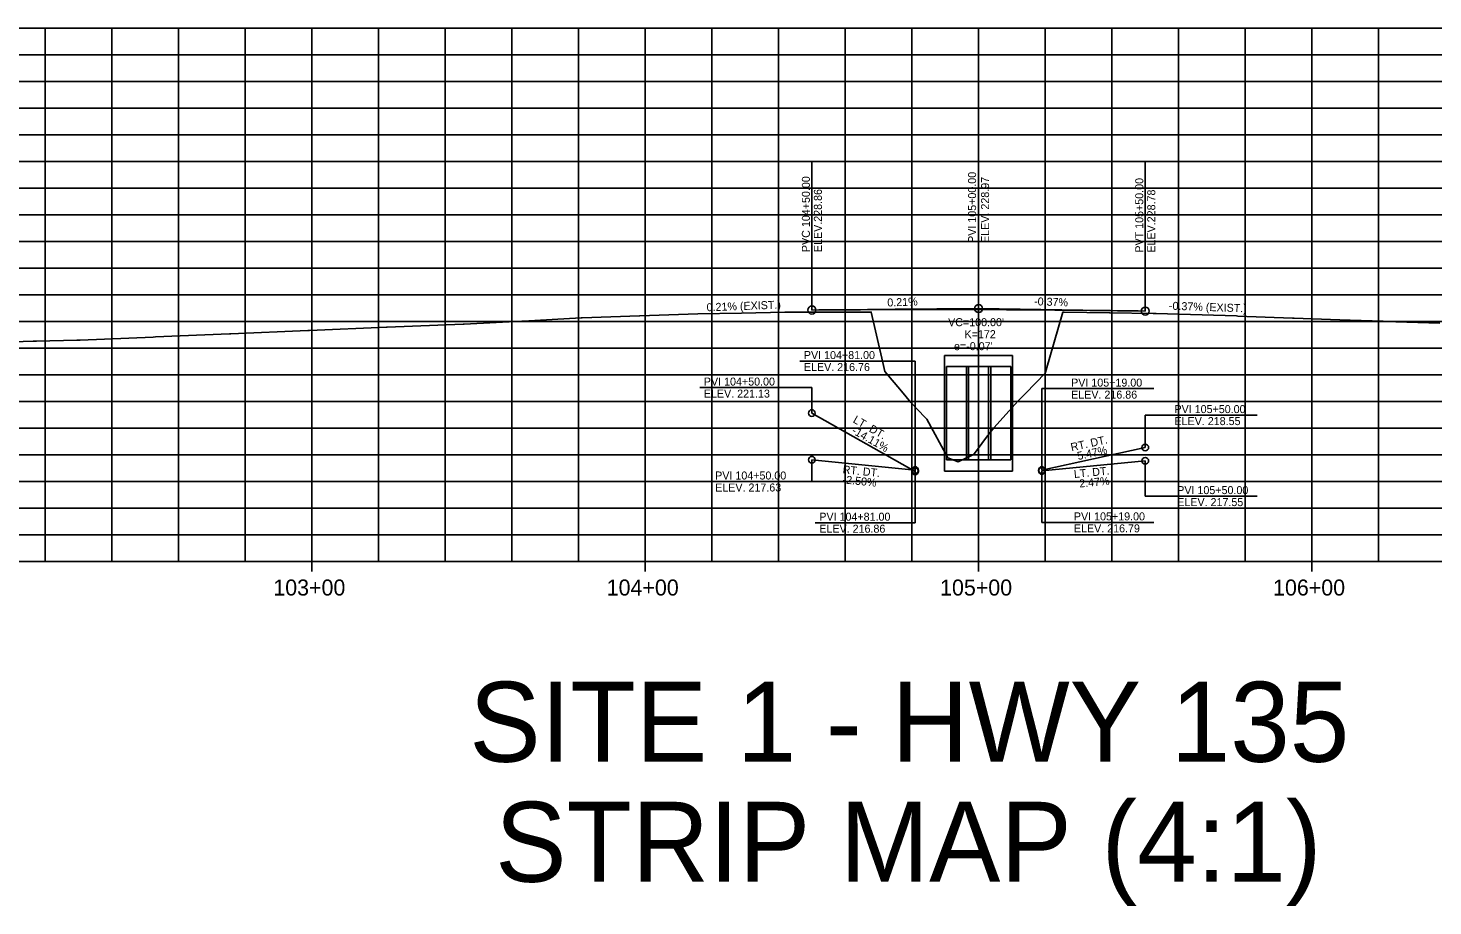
# Model space of a CAD drawing. Extents: x 1805251 to 1808760, y 516965 to 518393.
# Drawn here: x 1805687.1 to 1806108.5, y 518127.1 to 518390.4 of the extents above; entities that cross this region are included whole.
import ezdxf

# ---------------------------------------------------------------- set-up
doc = ezdxf.new("R2010")
doc.units = 0
for name, color, linetype in [('Default', 7, 'Continuous'), ('R_Axis', 7, 'Continuous'), ('R_Axis Annot', 7, 'Continuous'), ('R_Concrete', 7, 'Continuous'), ('R_Exist Surface', 7, 'Continuous'), ('R_Grid', 7, 'Continuous'), ('R_Vert Alg', 7, 'Continuous'), ('R_Vert Alg Annot', 7, 'Continuous')]:
    doc.layers.add(name, color=color, linetype=linetype)

msp = doc.modelspace()

# ---------------------------------------------------------------- linework, layer by layer
at = {"layer": 'R_Axis'}
msp.add_line((1805472.2, 518230.42), (1806472.2, 518230.42), dxfattribs=at)
at = {"layer": 'R_Concrete'}
for p, q in [((1805961.99, 518292.23), (1805982.41, 518292.23)), ((1805961.99, 518257.56), (1805961.99, 518292.23)), ((1805982.41, 518292.23), (1805982.41, 518257.56)), ((1805962.53, 518288.9), (1805981.87, 518288.9)), ((1805962.53, 518288.9), (1805962.53, 518260.9)), ((1805968.53, 518288.9), (1805968.53, 518260.9)), ((1805969.2, 518288.9), (1805969.2, 518260.9)), ((1805975.2, 518288.9), (1805975.2, 518260.9)), ((1805975.87, 518288.9), (1805975.87, 518260.9)), ((1805981.87, 518288.9), (1805981.87, 518260.9)), ((1805981.87, 518260.9), (1805962.53, 518260.9)), ((1805982.41, 518257.56), (1805961.99, 518257.56))]:
    msp.add_line(p, q, dxfattribs=at)
at = {"layer": 'R_Exist Surface'}
msp.add_lwpolyline([(1805676.49, 518296.16), (1805688.59, 518296.47), (1805689.59, 518296.49), (1805701.69, 518296.81), (1805702.68, 518296.84), (1805724.58, 518297.76), (1805725.32, 518297.79), (1805747.47, 518298.72), (1805747.96, 518298.75), (1805771.03, 518299.74), (1805771.46, 518299.76), (1805794.6, 518300.75), (1805794.8, 518300.76), (1805817.57, 518301.58), (1805817.91, 518301.59), (1805835.21, 518302.53), (1805835.6, 518302.55), (1805852.98, 518303.5), (1805853.3, 518303.51), (1805870.48, 518304.09), (1805870.64, 518304.1), (1805887.98, 518304.68), (1805888, 518304.68), (1805901.06, 518304.94), (1805901.08, 518304.94), (1805914.13, 518305.19), (1805914.17, 518305.19), (1805926.83, 518305.2), (1805927.09, 518305.21), (1805939.54, 518305.22), (1805940.02, 518305.23), (1805943.44, 518290.16), (1805944.09, 518287.4), (1805949.05, 518281.56), (1805951.9, 518278.14), (1805956.15, 518273.65), (1805956.64, 518273.14), (1805962.96, 518261.56), (1805962.97, 518261.53), (1805962.99, 518261.53), (1805966.1, 518260.34), (1805970.5, 518262.43), (1805970.66, 518262.45), (1805974.59, 518267.68), (1805976.76, 518270.55), (1805984.06, 518278.64), (1805984.14, 518278.72), (1805984.27, 518278.84), (1805986.23, 518280.85), (1805992.23, 518286.98), (1805992.46, 518287.88), (1805997.49, 518305.26), (1805997.91, 518305.25), (1806011.45, 518305.04), (1806011.66, 518305.04), (1806024.53, 518304.84), (1806025.42, 518304.83), (1806025.44, 518304.83), (1806049.53, 518304.07), (1806050, 518304.05), (1806066.4, 518303.44), (1806066.89, 518303.42), (1806083.26, 518302.81), (1806083.69, 518302.79), (1806096.89, 518302.38), (1806097.39, 518302.36), (1806110.51, 518301.95)], dxfattribs=at)
at = {"layer": 'R_Grid'}
for p, q in [((1805472.2, 518390.42), (1806472.2, 518390.42)), ((1805472.2, 518390.42), (1806472.2, 518390.42)), ((1805692.2, 518230.42), (1805692.2, 518390.42)), ((1805712.2, 518230.42), (1805712.2, 518390.42)), ((1805732.2, 518230.42), (1805732.2, 518390.42)), ((1805752.2, 518230.42), (1805752.2, 518390.42)), ((1805772.2, 518230.42), (1805772.2, 518390.42)), ((1805792.2, 518230.42), (1805792.2, 518390.42)), ((1805812.2, 518230.42), (1805812.2, 518390.42)), ((1805832.2, 518230.42), (1805832.2, 518390.42)), ((1805852.2, 518230.42), (1805852.2, 518390.42)), ((1805872.2, 518230.42), (1805872.2, 518390.42)), ((1805892.2, 518230.42), (1805892.2, 518390.42)), ((1805912.2, 518230.42), (1805912.2, 518390.42)), ((1805932.2, 518230.42), (1805932.2, 518390.42)), ((1805952.2, 518230.42), (1805952.2, 518390.42)), ((1805972.2, 518230.42), (1805972.2, 518390.42)), ((1805992.2, 518230.42), (1805992.2, 518390.42)), ((1806012.2, 518230.42), (1806012.2, 518390.42)), ((1806032.2, 518230.42), (1806032.2, 518390.42)), ((1806052.2, 518230.42), (1806052.2, 518390.42)), ((1806072.2, 518230.42), (1806072.2, 518390.42)), ((1806092.2, 518230.42), (1806092.2, 518390.42)), ((1805472.2, 518382.42), (1806472.2, 518382.42)), ((1805472.2, 518374.42), (1806472.2, 518374.42)), ((1805472.2, 518366.42), (1806472.2, 518366.42)), ((1805472.2, 518358.42), (1806472.2, 518358.42)), ((1805472.2, 518350.42), (1806472.2, 518350.42)), ((1805472.2, 518342.42), (1806472.2, 518342.42)), ((1805472.2, 518334.42), (1806472.2, 518334.42)), ((1805472.2, 518326.42), (1806472.2, 518326.42)), ((1805472.2, 518318.42), (1806472.2, 518318.42)), ((1805472.2, 518310.42), (1806472.2, 518310.42)), ((1805472.2, 518302.42), (1806472.2, 518302.42)), ((1805472.2, 518294.42), (1806472.2, 518294.42)), ((1805472.2, 518286.42), (1806472.2, 518286.42)), ((1805472.2, 518278.42), (1806472.2, 518278.42)), ((1805472.2, 518270.42), (1806472.2, 518270.42)), ((1805472.2, 518262.42), (1806472.2, 518262.42)), ((1805472.2, 518254.42), (1806472.2, 518254.42)), ((1805472.2, 518246.42), (1806472.2, 518246.42)), ((1805472.2, 518238.42), (1806472.2, 518238.42)), ((1805772.2, 518227.42), (1805772.2, 518230.42)), ((1805872.2, 518227.42), (1805872.2, 518230.42)), ((1805972.2, 518227.42), (1805972.2, 518230.42)), ((1806072.2, 518227.42), (1806072.2, 518230.42))]:
    msp.add_line(p, q, dxfattribs=at)
at = {"layer": 'R_Vert Alg'}
for p, q in [((1805947.2, 518306.07), (1805972.2, 518306.29)), ((1805972.2, 518306.29), (1805997.2, 518305.91)), ((1805922.2, 518274.95), (1805953.2, 518257.46)), ((1805991.2, 518257.86), (1806022.2, 518264.63)), ((1805922.2, 518260.95), (1805953.2, 518257.86)), ((1805991.2, 518257.58), (1806022.2, 518260.63))]:
    msp.add_line(p, q, dxfattribs=at)
msp.add_lwpolyline([(1805922.2, 518305.86), (1805924.28, 518305.88), (1805926.37, 518305.9), (1805928.45, 518305.91), (1805930.53, 518305.93), (1805932.62, 518305.94), (1805934.7, 518305.95), (1805936.78, 518305.96), (1805938.87, 518305.97), (1805940.95, 518305.98), (1805943.03, 518305.99), (1805945.12, 518306), (1805947.2, 518306), (1805949.28, 518306.01), (1805951.37, 518306.01), (1805953.45, 518306.01), (1805955.53, 518306.02), (1805957.62, 518306.02), (1805959.7, 518306.02), (1805961.78, 518306.02), (1805963.87, 518306.01), (1805965.95, 518306.01), (1805968.03, 518306.01), (1805970.12, 518306), (1805974.28, 518305.99), (1805976.37, 518305.98), (1805978.45, 518305.97), (1805980.53, 518305.96), (1805982.62, 518305.95), (1805984.7, 518305.94), (1805986.78, 518305.92), (1805988.87, 518305.91), (1805990.95, 518305.89), (1805993.03, 518305.88), (1805995.12, 518305.86), (1805997.2, 518305.84), (1805999.28, 518305.82), (1806001.37, 518305.8), (1806003.45, 518305.78), (1806005.53, 518305.76), (1806007.62, 518305.74), (1806009.7, 518305.71), (1806011.78, 518305.69), (1806013.87, 518305.66), (1806015.95, 518305.63), (1806018.03, 518305.6), (1806020.12, 518305.57), (1806022.2, 518305.54)], dxfattribs=at)
at = {"layer": 'R_Vert Alg Annot'}
for p, q in [((1805922.2, 518350.42), (1805922.2, 518305.86)), ((1805972.2, 518306.29), (1805972.2, 518350.42)), ((1806022.2, 518350.42), (1806022.2, 518305.54)), ((1805918.6, 518290.55), (1805953.2, 518290.55)), ((1805953.2, 518257.46), (1805953.2, 518290.55)), ((1805888.6, 518282.59), (1805922.2, 518282.59)), ((1805922.2, 518274.95), (1805922.2, 518282.59)), ((1805991.2, 518257.86), (1805991.2, 518282.28)), ((1805991.2, 518282.28), (1806024.8, 518282.28)), ((1806022.2, 518264.63), (1806022.2, 518274.34)), ((1806022.2, 518274.34), (1806055.8, 518274.34)), ((1805922.2, 518260.95), (1805922.2, 518254.42)), ((1806022.2, 518260.63), (1806022.2, 518250.04)), ((1805953.2, 518257.86), (1805953.2, 518242.06)), ((1805991.2, 518257.58), (1805991.2, 518242.16)), ((1805891.99, 518254.42), (1805922.2, 518254.42)), ((1806022.2, 518250.04), (1806055.8, 518250.04)), ((1805923.23, 518242.06), (1805953.2, 518242.06)), ((1805991.2, 518242.16), (1806024.8, 518242.16))]:
    msp.add_line(p, q, dxfattribs=at)
for centre, radius in [((1805922.2, 518305.86), 1.2), ((1805972.2, 518306.29), 1.2), ((1806022.2, 518305.54), 1.2), ((1805922.2, 518274.95), 1), ((1806022.2, 518264.63), 1), ((1805922.2, 518260.95), 1), ((1806022.2, 518260.63), 1), ((1805953.2, 518257.86), 1), ((1805953.2, 518257.46), 1), ((1805991.2, 518257.86), 1), ((1805991.2, 518257.58), 1)]:
    msp.add_circle(centre, radius, dxfattribs=at)

# ---------------------------------------------------------------- texts
at = {"layer": 'Default'}
for s, p in [('SITE 1 - HWY 135', (1805819.44, 518170.35)), ('STRIP MAP (4:1)', (1805827.19, 518134.35))]:
    msp.add_text(s, height=24, dxfattribs=at).set_placement(p)
at = {"layer": 'R_Axis Annot'}
for s, p in [('103+00', (1805760.66, 518220.22)), ('104+00', (1805860.66, 518220.22)), ('105+00', (1805960.66, 518220.22)), ('106+00', (1806060.54, 518220.22))]:
    msp.add_text(s, height=4.8, dxfattribs=at).set_placement(p)
at = {"layer": 'R_Vert Alg Annot'}
for s, rotation, p in [('PVC 104+50.00', 90, (1805921.6, 518323.23)), ('PVI 105+00.00', 90, (1805971.45, 518325.98)), ('ELEV. 228.97', 90, (1805975.35, 518325.98)), ('PVT 105+50.00', 90, (1806021.6, 518323.07)), ('ELEV.228.86', 90, (1805925.2, 518323.23)), ('ELEV.228.78', 90, (1806025.2, 518323.07)), ('0.21% (EXIST.)', 2.1461, (1805890.67, 518305.46)), ('0.21%', 2.1461, (1805944.87, 518306.9)), ('-0.37%', 358.0375, (1805988.82, 518307.29)), ('-0.37% (EXIST.)', 358.0375, (1806029.27, 518305.96)), ('LT. DT.', 330.557, (1805934.32, 518272.25)), ('-14.11%', 330.557, (1805933.97, 518269)), ('RT. DT.', 12.3349, (1806000.1, 518263.49)), ('5.47%', 12.3349, (1806002.08, 518260.85)), ('-2.50%', 354.2926, (1805931.34, 518253.87)), ('RT. DT.', 354.2926, (1805931.35, 518256.88)), ('LT. DT.', 5.6353, (1806000.91, 518255.46)), ('2.47%', 5.6353, (1806002.52, 518252.6))]:
    msp.add_text(s, height=2.4, rotation=rotation, dxfattribs=at).set_placement(p)
for s, p in [("VC=100.00'", (1805963.06, 518301.01)), ('K=172', (1805967.99, 518297.41)), ('PVI 104+81.00', (1805919.8, 518291.15)), ("e=-0.07'", (1805964.83, 518293.81)), ('ELEV. 216.76', (1805919.8, 518287.55)), ('PVI 104+50.00', (1805889.8, 518283.19)), ('PVI 105+19.00', (1805999.96, 518282.88)), ('ELEV. 221.13', (1805889.8, 518279.59)), ('ELEV. 216.86', (1805999.96, 518279.28)), ('PVI 105+50.00', (1806030.96, 518274.94)), ('ELEV. 218.55', (1806030.96, 518271.34)), ('PVI 104+50.00', (1805893.19, 518255.02)), ('ELEV. 217.63', (1805893.19, 518251.42)), ('PVI 105+50.00', (1806031.79, 518250.64)), ('ELEV. 217.55', (1806031.79, 518247.04)), ('PVI 104+81.00', (1805924.43, 518242.66)), ('PVI 105+19.00', (1806000.79, 518242.76)), ('ELEV. 216.86', (1805924.43, 518239.06)), ('ELEV. 216.79', (1806000.79, 518239.16))]:
    msp.add_text(s, height=2.4, dxfattribs=at).set_placement(p)

doc.saveas('drawing.dxf')
